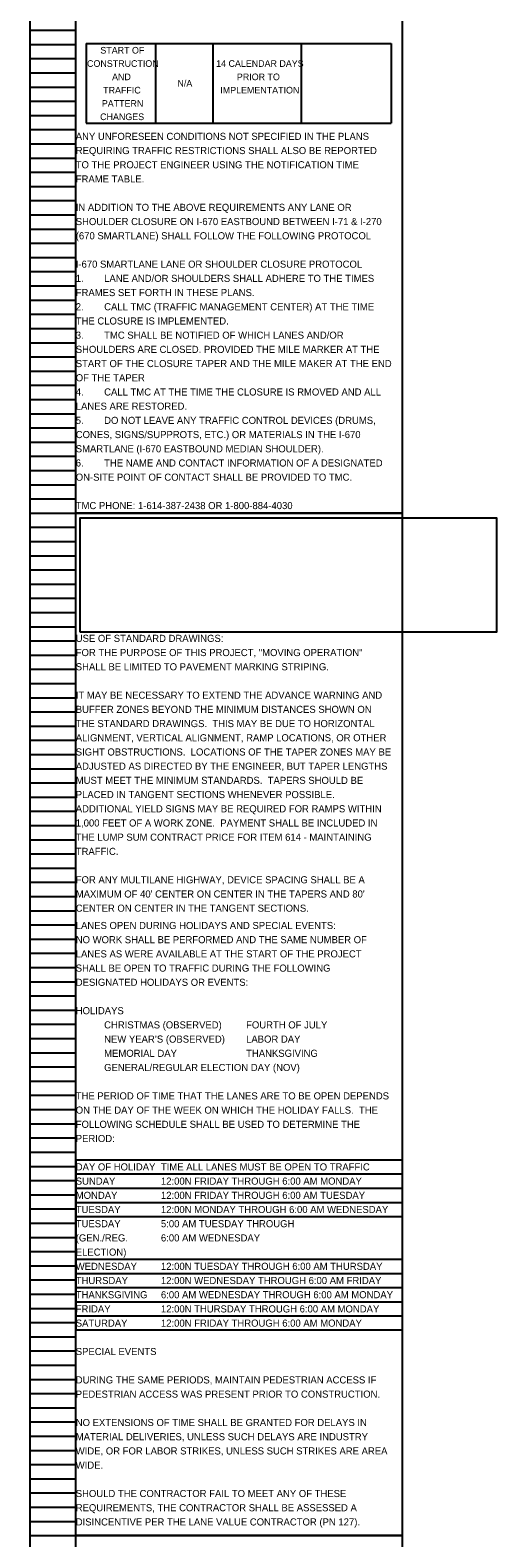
# Model space of a CAD drawing. Extents: x 16463 to 16500, y 5400 to 5823.
# Drawn here: x 16463.05 to 16472.25, y 5762.95 to 5792.67 of the extents above; entities that cross this region are included whole.
import ezdxf

# ---------------------------------------------------------------- set-up
doc = ezdxf.new("R2010")
doc.units = 0
for name, color, linetype in [('Default', 7, 'Continuous'), ('SC_Scratch1', 7, 'Continuous'), ('SH_Data', 7, 'Continuous')]:
    doc.layers.add(name, color=color, linetype=linetype)

msp = doc.modelspace()

# ---------------------------------------------------------------- linework, layer by layer
at = {"layer": 'Default'}
for p, q in [((16463.949, 5770.402), (16470.389, 5770.402)), ((16463.949, 5770.122), (16470.389, 5770.122)), ((16463.949, 5769.842), (16470.389, 5769.842)), ((16463.949, 5769.562), (16470.389, 5769.562)), ((16463.949, 5769.282), (16470.389, 5769.282)), ((16463.949, 5768.442), (16470.389, 5768.442)), ((16463.949, 5768.162), (16470.389, 5768.162)), ((16463.949, 5767.882), (16470.389, 5767.882)), ((16463.949, 5767.602), (16470.389, 5767.602)), ((16463.949, 5767.322), (16470.389, 5767.322))]:
    msp.add_line(p, q, dxfattribs=at)
msp.add_lwpolyline([(16464.031, 5780.811), (16472.255, 5780.811), (16472.255, 5783.05), (16464.031, 5783.05)], close=True, dxfattribs=at)
for points in [[(16463.949, 5770.402), (16470.389, 5770.402), (16470.389, 5767.051)], [(16463.949, 5770.402), (16463.949, 5767.051), (16470.389, 5767.051)]]:
    msp.add_lwpolyline(points, dxfattribs=at)
at = {"layer": 'SC_Scratch1'}
for points in [[(16463.949, 5803.312), (16470.389, 5803.312), (16470.389, 5783.152), (16463.949, 5783.152)], [(16463.949, 5783.152), (16470.389, 5783.152), (16470.389, 5762.992), (16463.949, 5762.992)], [(16463.949, 5783.152), (16470.389, 5783.152), (16470.389, 5762.992), (16463.949, 5762.992)], [(16463.949, 5762.992), (16470.389, 5762.992), (16470.389, 5742.832), (16463.949, 5742.832)]]:
    msp.add_lwpolyline(points, close=True, dxfattribs=at)
at = {"layer": 'SH_Data'}
for p, q in [((16463.049, 5783.152), (16463.049, 5803.312)), ((16463.949, 5783.152), (16463.949, 5803.312)), ((16463.049, 5792.672), (16463.949, 5792.672)), ((16463.049, 5792.392), (16463.949, 5792.392)), ((16464.152, 5792.413), (16470.17, 5792.413)), ((16464.152, 5792.413), (16464.152, 5790.839)), ((16465.525, 5792.413), (16465.525, 5790.839)), ((16466.652, 5792.413), (16466.652, 5790.839)), ((16468.396, 5792.413), (16468.396, 5790.839)), ((16470.17, 5792.413), (16470.17, 5790.839)), ((16463.049, 5792.112), (16463.949, 5792.112)), ((16463.049, 5791.832), (16463.949, 5791.832)), ((16463.049, 5791.552), (16463.949, 5791.552)), ((16463.049, 5791.272), (16463.949, 5791.272)), ((16463.049, 5790.992), (16463.949, 5790.992)), ((16464.152, 5790.839), (16470.17, 5790.839)), ((16463.049, 5790.712), (16463.949, 5790.712)), ((16463.049, 5790.432), (16463.949, 5790.432)), ((16463.049, 5790.152), (16463.949, 5790.152)), ((16463.049, 5789.872), (16463.949, 5789.872)), ((16463.049, 5789.592), (16463.949, 5789.592)), ((16463.049, 5789.312), (16463.949, 5789.312)), ((16463.049, 5789.032), (16463.949, 5789.032)), ((16463.049, 5788.752), (16463.949, 5788.752)), ((16463.049, 5788.472), (16463.949, 5788.472)), ((16463.049, 5788.192), (16463.949, 5788.192)), ((16463.049, 5787.912), (16463.949, 5787.912)), ((16463.049, 5787.632), (16463.949, 5787.632)), ((16463.049, 5787.352), (16463.949, 5787.352)), ((16463.049, 5787.072), (16463.949, 5787.072)), ((16463.049, 5786.792), (16463.949, 5786.792)), ((16463.049, 5786.512), (16463.949, 5786.512)), ((16463.049, 5786.232), (16463.949, 5786.232)), ((16463.049, 5785.952), (16463.949, 5785.952)), ((16463.049, 5785.672), (16463.949, 5785.672)), ((16463.049, 5785.392), (16463.949, 5785.392)), ((16463.049, 5785.112), (16463.949, 5785.112)), ((16463.049, 5784.832), (16463.949, 5784.832)), ((16463.049, 5784.552), (16463.949, 5784.552)), ((16463.049, 5784.272), (16463.949, 5784.272)), ((16463.049, 5783.992), (16463.949, 5783.992)), ((16463.049, 5783.712), (16463.949, 5783.712)), ((16463.049, 5783.432), (16463.949, 5783.432)), ((16463.049, 5762.992), (16463.049, 5783.152)), ((16463.049, 5783.152), (16463.949, 5783.152)), ((16463.049, 5783.152), (16463.949, 5783.152)), ((16463.949, 5762.992), (16463.949, 5783.152)), ((16463.049, 5782.872), (16463.949, 5782.872)), ((16463.049, 5782.592), (16463.949, 5782.592)), ((16463.049, 5782.312), (16463.949, 5782.312)), ((16463.049, 5782.032), (16463.949, 5782.032)), ((16463.049, 5781.752), (16463.949, 5781.752)), ((16463.049, 5781.472), (16463.949, 5781.472)), ((16463.049, 5781.192), (16463.949, 5781.192)), ((16463.049, 5780.912), (16463.949, 5780.912)), ((16463.049, 5780.632), (16463.949, 5780.632)), ((16463.049, 5780.352), (16463.949, 5780.352)), ((16463.049, 5780.072), (16463.949, 5780.072)), ((16463.049, 5779.792), (16463.949, 5779.792)), ((16463.049, 5779.512), (16463.949, 5779.512)), ((16463.049, 5779.232), (16463.949, 5779.232)), ((16463.049, 5778.952), (16463.949, 5778.952)), ((16463.049, 5778.672), (16463.949, 5778.672)), ((16463.049, 5778.392), (16463.949, 5778.392)), ((16463.049, 5778.112), (16463.949, 5778.112)), ((16463.049, 5777.832), (16463.949, 5777.832)), ((16463.049, 5777.552), (16463.949, 5777.552)), ((16463.049, 5777.272), (16463.949, 5777.272)), ((16463.049, 5776.992), (16463.949, 5776.992)), ((16463.049, 5776.712), (16463.949, 5776.712)), ((16463.049, 5776.432), (16463.949, 5776.432)), ((16463.049, 5776.152), (16463.949, 5776.152)), ((16463.049, 5775.872), (16463.949, 5775.872)), ((16463.049, 5775.592), (16463.949, 5775.592)), ((16463.049, 5775.312), (16463.949, 5775.312)), ((16463.049, 5775.032), (16463.949, 5775.032)), ((16463.049, 5774.752), (16463.949, 5774.752)), ((16463.049, 5774.472), (16463.949, 5774.472)), ((16463.049, 5774.192), (16463.949, 5774.192)), ((16463.049, 5773.912), (16463.949, 5773.912)), ((16463.049, 5773.632), (16463.949, 5773.632)), ((16463.049, 5773.352), (16463.949, 5773.352)), ((16463.049, 5773.072), (16463.949, 5773.072)), ((16463.049, 5772.792), (16463.949, 5772.792)), ((16463.049, 5772.512), (16463.949, 5772.512)), ((16463.049, 5772.232), (16463.949, 5772.232)), ((16463.049, 5771.952), (16463.949, 5771.952)), ((16463.049, 5771.672), (16463.949, 5771.672)), ((16463.049, 5771.392), (16463.949, 5771.392)), ((16463.049, 5771.112), (16463.949, 5771.112)), ((16463.049, 5770.832), (16463.949, 5770.832)), ((16463.049, 5770.552), (16463.949, 5770.552)), ((16463.049, 5770.272), (16463.949, 5770.272)), ((16463.049, 5769.992), (16463.949, 5769.992)), ((16463.049, 5769.712), (16463.949, 5769.712)), ((16463.049, 5769.432), (16463.949, 5769.432)), ((16463.049, 5769.152), (16463.949, 5769.152)), ((16463.049, 5768.872), (16463.949, 5768.872)), ((16463.049, 5768.592), (16463.949, 5768.592)), ((16463.049, 5768.312), (16463.949, 5768.312)), ((16463.049, 5768.032), (16463.949, 5768.032)), ((16463.049, 5767.752), (16463.949, 5767.752)), ((16463.049, 5767.472), (16463.949, 5767.472)), ((16463.049, 5767.192), (16463.949, 5767.192)), ((16463.049, 5766.912), (16463.949, 5766.912)), ((16463.049, 5766.632), (16463.949, 5766.632)), ((16463.049, 5766.352), (16463.949, 5766.352)), ((16463.049, 5766.072), (16463.949, 5766.072)), ((16463.049, 5765.792), (16463.949, 5765.792)), ((16463.049, 5765.512), (16463.949, 5765.512)), ((16463.049, 5765.232), (16463.949, 5765.232)), ((16463.049, 5764.952), (16463.949, 5764.952)), ((16463.049, 5764.672), (16463.949, 5764.672)), ((16463.049, 5764.392), (16463.949, 5764.392)), ((16463.049, 5764.112), (16463.949, 5764.112)), ((16463.049, 5763.832), (16463.949, 5763.832)), ((16463.049, 5763.552), (16463.949, 5763.552)), ((16463.049, 5763.272), (16463.949, 5763.272)), ((16463.049, 5742.832), (16463.049, 5762.992)), ((16463.049, 5762.992), (16463.949, 5762.992)), ((16463.049, 5762.992), (16463.949, 5762.992)), ((16463.949, 5742.832), (16463.949, 5762.992))]:
    msp.add_line(p, q, dxfattribs=at)

# ---------------------------------------------------------------- texts
at = {"layer": 'Default'}
for s, p in [('ANY UNFORESEEN CONDITIONS NOT SPECIFIED IN THE PLANS ', (16463.949, 5790.51)), ('REQUIRING TRAFFIC RESTRICTIONS SHALL ALSO BE REPORTED ', (16463.949, 5790.23)), ('TO THE PROJECT ENGINEER USING THE NOTIFICATION TIME ', (16463.949, 5789.95)), ('FRAME TABLE. ', (16463.949, 5789.67)), ('IN ADDITION TO THE ABOVE REQUIREMENTS ANY LANE OR ', (16463.949, 5789.11)), ('SHOULDER CLOSURE ON I-670 EASTBOUND BETWEEN I-71 & I-270 ', (16463.949, 5788.83)), ('(670 SMARTLANE) SHALL FOLLOW THE FOLLOWING PROTOCOL ', (16463.949, 5788.55)), ('I-670 SMARTLANE LANE OR SHOULDER CLOSURE PROTOCOL', (16463.949, 5787.99)), ('1.', (16463.949, 5787.71)), ('LANE AND/OR SHOULDERS SHALL ADHERE TO THE TIMES ', (16464.509, 5787.71)), ('FRAMES SET FORTH IN THESE PLANS.', (16463.949, 5787.43)), ('2.', (16463.949, 5787.15)), ('CALL TMC (TRAFFIC MANAGEMENT CENTER) AT THE TIME ', (16464.509, 5787.15)), ('THE CLOSURE IS IMPLEMENTED.', (16463.949, 5786.87)), ('3.', (16463.949, 5786.59)), ('TMC SHALL BE NOTIFIED OF WHICH LANES AND/OR ', (16464.509, 5786.59)), ('SHOULDERS ARE CLOSED. PROVIDED THE MILE MARKER AT THE ', (16463.949, 5786.31)), ('START OF THE CLOSURE TAPER AND THE MILE MAKER AT THE END ', (16463.949, 5786.03)), ('OF THE TAPER', (16463.949, 5785.75)), ('4.', (16463.949, 5785.47)), ('CALL TMC AT THE TIME THE CLOSURE IS RMOVED AND ALL ', (16464.509, 5785.47)), ('LANES ARE RESTORED. ', (16463.949, 5785.19)), ('5.', (16463.949, 5784.91)), ('DO NOT LEAVE ANY TRAFFIC CONTROL DEVICES (DRUMS, ', (16464.509, 5784.91)), ('CONES, SIGNS/SUPPROTS, ETC.) OR MATERIALS IN THE I-670 ', (16463.949, 5784.63)), ('SMARTLANE (I-670 EASTBOUND MEDIAN SHOULDER).', (16463.949, 5784.35)), ('ON-SITE POINT OF CONTACT SHALL BE PROVIDED TO TMC.', (16463.949, 5783.79)), ('6.', (16463.949, 5784.07)), ('THE NAME AND CONTACT INFORMATION OF A DESIGNATED ', (16464.509, 5784.07)), ('TMC PHONE: 1-614-387-2438 OR 1-800-884-4030 ', (16463.949, 5783.23)), ('USE OF STANDARD DRAWINGS:', (16463.949, 5780.612)), ('FOR THE PURPOSE OF THIS PROJECT, "MOVING OPERATION" ', (16463.949, 5780.332)), ('SHALL BE LIMITED TO PAVEMENT MARKING STRIPING.', (16463.949, 5780.052)), ('IT MAY BE NECESSARY TO EXTEND THE ADVANCE WARNING AND ', (16463.949, 5779.492)), ('BUFFER ZONES BEYOND THE MINIMUM DISTANCES SHOWN ON ', (16463.949, 5779.212)), ('THE STANDARD DRAWINGS.  THIS MAY BE DUE TO HORIZONTAL ', (16463.949, 5778.932)), ('ALIGNMENT, VERTICAL ALIGNMENT, RAMP LOCATIONS, OR OTHER ', (16463.949, 5778.652)), ('SIGHT OBSTRUCTIONS.  LOCATIONS OF THE TAPER ZONES MAY BE ', (16463.949, 5778.372)), ('ADJUSTED AS DIRECTED BY THE ENGINEER, BUT TAPER LENGTHS ', (16463.949, 5778.092)), ('MUST MEET THE MINIMUM STANDARDS.  TAPERS SHOULD BE ', (16463.949, 5777.812)), ('ADDITIONAL YIELD SIGNS MAY BE REQUIRED FOR RAMPS WITHIN ', (16463.949, 5777.252)), ('PLACED IN TANGENT SECTIONS WHENEVER POSSIBLE.  ', (16463.949, 5777.532)), ('1,000 FEET OF A WORK ZONE.  PAYMENT SHALL BE INCLUDED IN ', (16463.949, 5776.972)), ('THE LUMP SUM CONTRACT PRICE FOR ITEM 614 - MAINTAINING ', (16463.949, 5776.692)), ('TRAFFIC.', (16463.949, 5776.412)), ('FOR ANY MULTILANE HIGHWAY, DEVICE SPACING SHALL BE A ', (16463.949, 5775.852)), ("MAXIMUM OF 40' CENTER ON CENTER IN THE TAPERS AND 80' ", (16463.949, 5775.572)), ('CENTER ON CENTER IN THE TANGENT SECTIONS.', (16463.949, 5775.292)), ('LANES OPEN DURING HOLIDAYS AND SPECIAL EVENTS:', (16463.949, 5774.951)), ('NO WORK SHALL BE PERFORMED AND THE SAME NUMBER OF ', (16463.949, 5774.671)), ('LANES AS WERE AVAILABLE AT THE START OF THE PROJECT ', (16463.949, 5774.391)), ('SHALL BE OPEN TO TRAFFIC DURING THE FOLLOWING ', (16463.949, 5774.111)), ('DESIGNATED HOLIDAYS OR EVENTS:', (16463.949, 5773.831)), ('HOLIDAYS', (16463.949, 5773.271)), ('CHRISTMAS (OBSERVED)', (16464.509, 5772.991)), ('FOURTH OF JULY', (16467.309, 5772.991)), ('NEW YEAR’S (OBSERVED)', (16464.509, 5772.711)), ('LABOR DAY', (16467.309, 5772.711)), ('MEMORIAL DAY          ', (16464.509, 5772.431)), ('THANKSGIVING', (16467.309, 5772.431)), ('GENERAL/REGULAR ELECTION DAY (NOV)', (16464.509, 5772.151)), ('THE PERIOD OF TIME THAT THE LANES ARE TO BE OPEN DEPENDS ', (16463.949, 5771.591)), ('ON THE DAY OF THE WEEK ON WHICH THE HOLIDAY FALLS.  THE ', (16463.949, 5771.311)), ('FOLLOWING SCHEDULE SHALL BE USED TO DETERMINE THE ', (16463.949, 5771.031)), ('PERIOD:', (16463.949, 5770.751)), ('DAY OF HOLIDAY', (16463.949, 5770.191)), ('TIME ALL LANES MUST BE OPEN TO TRAFFIC', (16465.629, 5770.191)), ('SUNDAY', (16463.949, 5769.911)), ('12:00N FRIDAY THROUGH 6:00 AM MONDAY', (16465.629, 5769.911)), ('MONDAY', (16463.949, 5769.631)), ('12:00N FRIDAY THROUGH 6:00 AM TUESDAY', (16465.629, 5769.631)), ('TUESDAY', (16463.949, 5769.351)), ('12:00N MONDAY THROUGH 6:00 AM WEDNESDAY', (16465.629, 5769.351)), ('TUESDAY', (16463.949, 5769.071)), ('5:00 AM TUESDAY THROUGH  ', (16465.629, 5769.071)), ('(GEN./REG.', (16463.949, 5768.791)), ('6:00 AM WEDNESDAY', (16465.629, 5768.791)), ('ELECTION)', (16463.949, 5768.511)), ('WEDNESDAY', (16463.949, 5768.231)), ('12:00N TUESDAY THROUGH 6:00 AM THURSDAY', (16465.629, 5768.231)), ('THURSDAY', (16463.949, 5767.951)), ('12:00N WEDNESDAY THROUGH 6:00 AM FRIDAY', (16465.629, 5767.951)), ('THANKSGIVING', (16463.949, 5767.671)), ('6:00 AM WEDNESDAY THROUGH 6:00 AM MONDAY', (16465.629, 5767.671)), ('FRIDAY', (16463.949, 5767.391)), ('12:00N THURSDAY THROUGH 6:00 AM MONDAY', (16465.629, 5767.391)), ('SATURDAY', (16463.949, 5767.111)), ('12:00N FRIDAY THROUGH 6:00 AM MONDAY', (16465.629, 5767.111)), ('SPECIAL EVENTS', (16463.949, 5766.551)), ('DURING THE SAME PERIODS, MAINTAIN PEDESTRIAN ACCESS IF ', (16463.949, 5765.991)), ('PEDESTRIAN ACCESS WAS PRESENT PRIOR TO CONSTRUCTION.', (16463.949, 5765.711)), ('NO EXTENSIONS OF TIME SHALL BE GRANTED FOR DELAYS IN ', (16463.949, 5765.151)), ('MATERIAL DELIVERIES, UNLESS SUCH DELAYS ARE INDUSTRY ', (16463.949, 5764.871)), ('WIDE, OR FOR LABOR STRIKES, UNLESS SUCH STRIKES ARE AREA ', (16463.949, 5764.591)), ('WIDE.', (16463.949, 5764.311)), ('SHOULD THE CONTRACTOR FAIL TO MEET ANY OF THESE ', (16463.949, 5763.751)), ('REQUIREMENTS, THE CONTRACTOR SHALL BE ASSESSED A ', (16463.949, 5763.471)), ('DISINCENTIVE PER THE LANE VALUE CONTRACTOR (PN 127).', (16463.949, 5763.191))]:
    msp.add_text(s, height=0.14, dxfattribs=at).set_placement(p)
at = {"layer": 'SH_Data'}
for s, height, p in [('START OF', 0.1312, (16464.434, 5792.212)), ('CONSTRUCTION', 0.13117, (16464.172, 5791.95)), ('14 CALENDAR DAYS', 0.13117, (16466.718, 5791.95)), ('AND', 0.1312, (16464.665, 5791.687)), ('N/A', 0.1312, (16465.955, 5791.56)), ('PRIOR TO', 0.1312, (16467.127, 5791.687)), ('TRAFFIC', 0.1312, (16464.49, 5791.425)), ('IMPLEMENTATION', 0.13117, (16466.8, 5791.425)), ('PATTERN', 0.1312, (16464.463, 5791.163)), ('CHANGES', 0.1312, (16464.43, 5790.9))]:
    msp.add_text(s, height=height, dxfattribs=at).set_placement(p)

doc.saveas('drawing.dxf')
